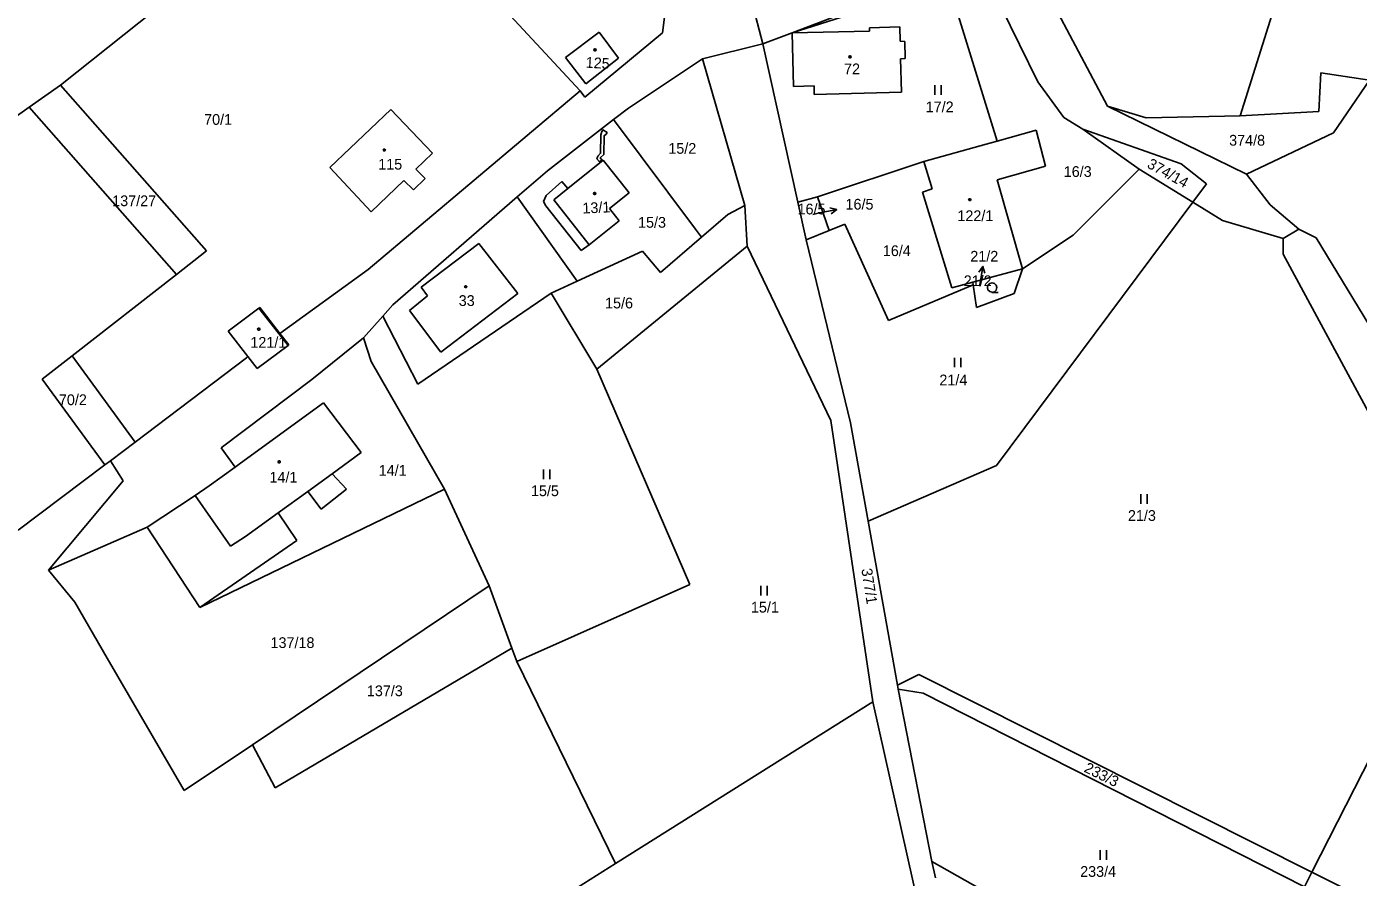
# Model space of a CAD drawing. Extents: x -811039 to -805820, y -1161436 to -1155864.
# Drawn here: x -806771.7 to -806560.9, y -1158370.8 to -1158236.2 of the extents above; entities that cross this region are included whole.
import ezdxf

# ---------------------------------------------------------------- set-up
doc = ezdxf.new("R2010")
doc.units = 0
for name, color, linetype in [('Default', 7, 'Continuous'), ('Hranice parcel', 7, 'Continuous'), ('Parcelní čísla', 7, 'Continuous'), ('Pop  PČ popisy', 7, 'Continuous'), ('Vnitřní kresba', 7, 'Continuous'), ('Věcná břemena k části', 7, 'Continuous'), ('Značky budov', 7, 'Continuous'), ('Značky kultur', 7, 'Continuous')]:
    doc.layers.add(name, color=color, linetype=linetype)

# ---------------------------------------------------------------- blocks, each defined once
blk = doc.blocks.new('304')
at = {"layer": 'Default'}
blk.add_lwpolyline([(0, 0), (-0.38, 0.1), (-0.65, 0.37), (-0.75, 0.74), (-0.65, 1.11), (-0.38, 1.38), (-0.01, 1.48), (0.36, 1.38), (0.63, 1.11), (0.73, 0.73), (0.63, 0.35), (0.36, 0.08), (-0.02, -0.02), (0.98, -0.02)], dxfattribs=at)
blk = doc.blocks.new('306')
at = {"layer": 'Default'}
for p, q in [((-0.5, 1.5), (-0.5, 0)), ((0.5, 0), (0.5, 1.5))]:
    blk.add_line(p, q, dxfattribs=at)
blk = doc.blocks.new('10292')
at = {"layer": 'Default'}
blk.add_line((0, 3), (0, 0), dxfattribs=at)
blk.add_lwpolyline([(-0.5, 2), (0, 3), (0.5, 2)], dxfattribs=at)
blk = doc.blocks.new('402')
at = {"layer": 'Default'}
blk.add_lwpolyline([(0.09, 0.15), (0.18, 0), (0.09, -0.15), (-0.09, -0.15), (-0.18, 0), (-0.09, 0.15), (0.09, 0.15)], dxfattribs=at)

msp = doc.modelspace()

# ---------------------------------------------------------------- linework, layer by layer
at = {"layer": 'Hranice parcel'}
for p, q in [((-806569.88, -1158219.21), (-806579.62, -1158250.35)), ((-806614.52, -1158222.57), (-806600.61, -1158248.81)), ((-806701.18, -1158227.97), (-806684.08, -1158246.35)), ((-806626.33, -1158227.96), (-806650.49, -1158237.2)), ((-806625.78, -1158229.31), (-806650.49, -1158237.2)), ((-806625.78, -1158229.31), (-806618.07, -1158254.33)), ((-806766.34, -1158245.5), (-806751.34, -1158233.56)), ((-806611.64, -1158244.97), (-806617.42, -1158233.13)), ((-806671.05, -1158237.22), (-806670.66, -1158234.29)), ((-806656.32, -1158234.5), (-806655.17, -1158238.94)), ((-806686.4, -1158241.1), (-806681.08, -1158237.07)), ((-806683.35, -1158247.36), (-806671.05, -1158237.22)), ((-806681.08, -1158237.07), (-806677.98, -1158241.18)), ((-806650.49, -1158237.2), (-806655.17, -1158238.94)), ((-806650.49, -1158237.2), (-806638.26, -1158236.95)), ((-806650.49, -1158237.2), (-806650.31, -1158245.68)), ((-806638.28, -1158236.39), (-806633.47, -1158236.25)), ((-806638.26, -1158236.95), (-806638.28, -1158236.39)), ((-806633.47, -1158236.25), (-806633.41, -1158238.54)), ((-806664.69, -1158241.33), (-806655.17, -1158238.94)), ((-806655.17, -1158238.94), (-806649.62, -1158263.99)), ((-806633.41, -1158238.54), (-806632.7, -1158238.55)), ((-806632.7, -1158238.55), (-806632.65, -1158241.28)), ((-806683.16, -1158245.26), (-806686.4, -1158241.1)), ((-806677.98, -1158241.18), (-806683.16, -1158245.26)), ((-806676.42, -1158249.09), (-806664.69, -1158241.33)), ((-806664.69, -1158241.33), (-806657.99, -1158264.53)), ((-806632.65, -1158241.28), (-806633.35, -1158241.33)), ((-806633.35, -1158241.33), (-806633.22, -1158246.57)), ((-806566.82, -1158243.53), (-806567.15, -1158249.63)), ((-806559.13, -1158244.68), (-806566.82, -1158243.53)), ((-806771.28, -1158248.97), (-806766.34, -1158245.5)), ((-806743.22, -1158271.7), (-806766.34, -1158245.5)), ((-806717.64, -1158274.65), (-806684.08, -1158246.35)), ((-806684.08, -1158246.35), (-806683.35, -1158247.36)), ((-806647.05, -1158245.59), (-806650.31, -1158245.68)), ((-806647.02, -1158246.96), (-806647.05, -1158245.59)), ((-806633.22, -1158246.57), (-806647.02, -1158246.96)), ((-806607.53, -1158250.61), (-806611.64, -1158244.97)), ((-806564.83, -1158253.03), (-806559.13, -1158244.68)), ((-806600.61, -1158248.81), (-806594.47, -1158250.63)), ((-806578.58, -1158259.54), (-806600.61, -1158248.81)), ((-806844.14, -1158300.03), (-806771.28, -1158248.97)), ((-806771.28, -1158248.97), (-806747.96, -1158275.4)), ((-806723.67, -1158258.49), (-806714.03, -1158249.32)), ((-806714.03, -1158249.32), (-806707.44, -1158256.22)), ((-806678.79, -1158250.93), (-806689.25, -1158259.04)), ((-806678.79, -1158250.93), (-806676.42, -1158249.09)), ((-806678.79, -1158250.93), (-806665.8, -1158268.27)), ((-806604.52, -1158252.42), (-806607.53, -1158250.61)), ((-806594.47, -1158250.63), (-806579.62, -1158250.35)), ((-806567.15, -1158249.63), (-806579.62, -1158250.35)), ((-806618.07, -1158254.33), (-806611.9, -1158252.58)), ((-806610.42, -1158258.3), (-806611.9, -1158252.58)), ((-806595.61, -1158258.78), (-806604.52, -1158252.42)), ((-806604.52, -1158252.42), (-806588.94, -1158257.91)), ((-806578.58, -1158259.54), (-806564.83, -1158253.03)), ((-806629.7, -1158257.57), (-806619.79, -1158254.82)), ((-806619.79, -1158254.82), (-806618.07, -1158254.33)), ((-806707.44, -1158256.22), (-806710.08, -1158258.75)), ((-806723.67, -1158258.49), (-806717.14, -1158265.51)), ((-806710.08, -1158258.75), (-806708.63, -1158260.25)), ((-806689.25, -1158259.04), (-806694.03, -1158263.13)), ((-806686.04, -1158261.84), (-806680.41, -1158257.34)), ((-806680.41, -1158257.34), (-806676.3, -1158262.5)), ((-806629.7, -1158257.57), (-806646.48, -1158263.13)), ((-806628.38, -1158261.89), (-806629.7, -1158257.57)), ((-806618.08, -1158260.43), (-806610.42, -1158258.3)), ((-806606.02, -1158269.18), (-806595.61, -1158258.78)), ((-806587.11, -1158264), (-806595.61, -1158258.78)), ((-806588.94, -1158257.91), (-806584.95, -1158261.1)), ((-806711.97, -1158260.56), (-806717.14, -1158265.51)), ((-806710.46, -1158262.04), (-806711.97, -1158260.56)), ((-806708.63, -1158260.25), (-806710.46, -1158262.04)), ((-806689.43, -1158262.92), (-806686.97, -1158260.72)), ((-806686.97, -1158260.72), (-806686.04, -1158261.84)), ((-806618.08, -1158260.43), (-806614.08, -1158274.51)), ((-806584.95, -1158261.1), (-806587.11, -1158264)), ((-806578.58, -1158259.54), (-806574.85, -1158264.38)), ((-806713.73, -1158280.2), (-806694.03, -1158263.13)), ((-806684.52, -1158276.47), (-806694.03, -1158263.13)), ((-806689.43, -1158262.92), (-806689.88, -1158263.88)), ((-806676.3, -1158262.5), (-806679.43, -1158265)), ((-806646.48, -1158263.13), (-806649.62, -1158263.99)), ((-806646.48, -1158263.13), (-806644.64, -1158268.47)), ((-806629.91, -1158262.41), (-806628.38, -1158261.89)), ((-806629.91, -1158262.41), (-806625.23, -1158277.52)), ((-806689.49, -1158264.59), (-806689.88, -1158263.88)), ((-806683.89, -1158271.65), (-806689.49, -1158264.59)), ((-806679.43, -1158265), (-806677.9, -1158266.93)), ((-806660.68, -1158265.92), (-806657.99, -1158264.53)), ((-806657.99, -1158264.53), (-806657.64, -1158270.92)), ((-806649.62, -1158263.99), (-806648.3, -1158269.92)), ((-806618.18, -1158305.63), (-806587.11, -1158264)), ((-806582.39, -1158266.9), (-806587.11, -1158264)), ((-806574.85, -1158264.38), (-806570.3, -1158268.26)), ((-806677.9, -1158266.93), (-806682.66, -1158270.72)), ((-806664.86, -1158269.51), (-806660.68, -1158265.92)), ((-806644.64, -1158268.47), (-806642.16, -1158267.49)), ((-806635.29, -1158282.7), (-806642.16, -1158267.49)), ((-806572.81, -1158269.71), (-806582.39, -1158266.9)), ((-806671.36, -1158275.11), (-806664.86, -1158269.51)), ((-806665.8, -1158268.27), (-806664.86, -1158269.51)), ((-806648.3, -1158269.92), (-806644.64, -1158268.47)), ((-806641.29, -1158298.89), (-806648.3, -1158269.92)), ((-806606.02, -1158269.18), (-806614.08, -1158274.51)), ((-806572.81, -1158269.71), (-806570.3, -1158268.26)), ((-806572.8, -1158272.22), (-806572.81, -1158269.71)), ((-806570.3, -1158268.26), (-806567.55, -1158269.62)), ((-806567.55, -1158269.62), (-806558.32, -1158284.79)), ((-806747.96, -1158275.4), (-806743.22, -1158271.7)), ((-806684.52, -1158276.47), (-806674.23, -1158271.75)), ((-806682.66, -1158270.72), (-806683.89, -1158271.65)), ((-806657.64, -1158270.92), (-806681.44, -1158290.41)), ((-806674.23, -1158271.75), (-806671.36, -1158275.11)), ((-806657.64, -1158270.92), (-806644.38, -1158298.52)), ((-806544.86, -1158324.01), (-806572.8, -1158272.22)), ((-806764.5, -1158288.31), (-806747.96, -1158275.4)), ((-806717.64, -1158274.65), (-806731.62, -1158284.78)), ((-806614.08, -1158274.51), (-806621.9, -1158276.62)), ((-806615.4, -1158278.42), (-806614.08, -1158274.51)), ((-806709.75, -1158292.76), (-806688.67, -1158278.37)), ((-806688.67, -1158278.37), (-806684.52, -1158276.47)), ((-806681.44, -1158290.41), (-806688.67, -1158278.37)), ((-806635.29, -1158282.7), (-806621.84, -1158277.08)), ((-806621.9, -1158276.62), (-806625.23, -1158277.52)), ((-806621.84, -1158277.08), (-806621.9, -1158276.62)), ((-806621.84, -1158277.08), (-806621.36, -1158280.63)), ((-806715.31, -1158282), (-806713.73, -1158280.2)), ((-806621.36, -1158280.63), (-806615.4, -1158278.42)), ((-806739.78, -1158284.38), (-806734.91, -1158280.74)), ((-806734.91, -1158280.74), (-806734.79, -1158280.65)), ((-806734.79, -1158280.65), (-806731.62, -1158284.78)), ((-806718.34, -1158285.46), (-806715.31, -1158282)), ((-806715.31, -1158282), (-806709.75, -1158292.76)), ((-806736.68, -1158288.42), (-806739.78, -1158284.38)), ((-806730.31, -1158286.64), (-806735.22, -1158290.32)), ((-806731.62, -1158284.78), (-806730.19, -1158286.55)), ((-806730.31, -1158286.64), (-806730.19, -1158286.55)), ((-806718.34, -1158285.46), (-806726.53, -1158292.04)), ((-806718.34, -1158285.46), (-806717.16, -1158289.2)), ((-806769.23, -1158292), (-806764.5, -1158288.31)), ((-806764.5, -1158288.31), (-806754.53, -1158301.94)), ((-806736.89, -1158288.6), (-806754.53, -1158301.94)), ((-806736.68, -1158288.42), (-806736.89, -1158288.6)), ((-806735.22, -1158290.32), (-806736.68, -1158288.42)), ((-806705.56, -1158309.37), (-806717.16, -1158289.2)), ((-806681.44, -1158290.41), (-806666.71, -1158324.45)), ((-806759.33, -1158305.54), (-806769.23, -1158292)), ((-806726.53, -1158292.04), (-806740.91, -1158302.82)), ((-806724.7, -1158295.75), (-806737.81, -1158305.26)), ((-806724.7, -1158295.75), (-806718.75, -1158303.59)), ((-806644.38, -1158298.52), (-806637.75, -1158343)), ((-806641.29, -1158298.89), (-806638.49, -1158314.46)), ((-806754.53, -1158301.94), (-806758.42, -1158304.88)), ((-806740.91, -1158302.82), (-806738.67, -1158305.89)), ((-806718.75, -1158303.59), (-806723.3, -1158306.96)), ((-806773.03, -1158315.88), (-806759.33, -1158305.54)), ((-806758.42, -1158304.88), (-806759.33, -1158305.54)), ((-806758.42, -1158304.88), (-806756.43, -1158308.08)), ((-806737.81, -1158305.26), (-806738.67, -1158305.89)), ((-806638.49, -1158314.46), (-806618.18, -1158305.63)), ((-806738.67, -1158305.89), (-806742.78, -1158308.87)), ((-806723.3, -1158306.96), (-806721.06, -1158309.4)), ((-806756.43, -1158308.08), (-806768.24, -1158322.22)), ((-806745.03, -1158310.37), (-806742.78, -1158308.87)), ((-806705.56, -1158309.37), (-806744.29, -1158328.1)), ((-806727.16, -1158309.73), (-806731.85, -1158313.12)), ((-806725.08, -1158312.56), (-806727.16, -1158309.73)), ((-806721.06, -1158309.4), (-806725.08, -1158312.56)), ((-806698.45, -1158324.65), (-806705.56, -1158309.37)), ((-806752.62, -1158315.42), (-806745.03, -1158310.37)), ((-806731.85, -1158313.12), (-806728.91, -1158317.51)), ((-806752.62, -1158315.42), (-806768.24, -1158322.22)), ((-806744.29, -1158328.1), (-806752.62, -1158315.42)), ((-806638.49, -1158314.46), (-806633.84, -1158340.37)), ((-806728.91, -1158317.51), (-806744.29, -1158328.1)), ((-806764.06, -1158327.28), (-806768.24, -1158322.22)), ((-806698.45, -1158324.65), (-806735.95, -1158349.81)), ((-806694.87, -1158334.56), (-806698.45, -1158324.65)), ((-806666.71, -1158324.45), (-806694.12, -1158336.64)), ((-806568.24, -1158369.98), (-806544.86, -1158324.01)), ((-806764.06, -1158327.28), (-806758.94, -1158336.1)), ((-806694.87, -1158334.56), (-806732.36, -1158356.65)), ((-806694.12, -1158336.64), (-806694.87, -1158334.56)), ((-806758.94, -1158336.1), (-806746.75, -1158357.06)), ((-806678.47, -1158368.59), (-806694.12, -1158336.64)), ((-806633.84, -1158340.37), (-806630.46, -1158338.72)), ((-806568.24, -1158369.98), (-806630.46, -1158338.72)), ((-806633.73, -1158341), (-806633.84, -1158340.37)), ((-806628.39, -1158368.28), (-806633.73, -1158341)), ((-806633.73, -1158341), (-806629.79, -1158341.63)), ((-806629.79, -1158341.63), (-806569.41, -1158372.27)), ((-806637.75, -1158343), (-806678.47, -1158368.59)), ((-806624.17, -1158403.51), (-806637.75, -1158343)), ((-806746.75, -1158357.06), (-806735.95, -1158349.81)), ((-806732.36, -1158356.65), (-806735.95, -1158349.81)), ((-806678.47, -1158368.59), (-806701.28, -1158382.95)), ((-806588.22, -1158390.98), (-806628.39, -1158368.28)), ((-806628.39, -1158368.28), (-806627.84, -1158370.88)), ((-806569.41, -1158372.27), (-806568.24, -1158369.98)), ((-806558.16, -1158375.01), (-806568.24, -1158369.98))]:
    msp.add_line(p, q, dxfattribs=at)
at = {"layer": 'Pop  PČ popisy'}
for p, q in [((-806647.22, -1158265.92), (-806646.4, -1158265.75)), ((-806620.82, -1158277.27), (-806620.8, -1158277.11))]:
    msp.add_line(p, q, dxfattribs=at)
at = {"layer": 'Vnitřní kresba'}
for p, q in [((-806686.04, -1158261.84), (-806688.23, -1158263.6)), ((-806688.23, -1158263.6), (-806682.66, -1158270.72)), ((-806709.22, -1158277.41), (-806700.11, -1158270.52)), ((-806700.11, -1158270.52), (-806693.93, -1158278.43)), ((-806709.22, -1158277.41), (-806708.23, -1158278.8)), ((-806708.23, -1158278.8), (-806711.11, -1158281.13)), ((-806693.93, -1158278.43), (-806706.13, -1158287.7)), ((-806730.31, -1158286.64), (-806734.91, -1158280.74)), ((-806706.13, -1158287.7), (-806711.11, -1158281.13)), ((-806723.3, -1158306.96), (-806727.16, -1158309.73)), ((-806739.44, -1158318.4), (-806745.03, -1158310.37)), ((-806731.85, -1158313.12), (-806737.02, -1158316.88)), ((-806737.02, -1158316.88), (-806739.44, -1158318.4))]:
    msp.add_line(p, q, dxfattribs=at)
at = {"layer": 'Věcná břemena k části'}
msp.add_lwpolyline([(-806681.03, -1158257.61), (-806681.42, -1158257.11), (-806681.29, -1158256.69), (-806680.85, -1158256.25), (-806680.79, -1158253.31), (-806680.64, -1158252.8), (-806680.49, -1158252.55), (-806679.82, -1158252.98), (-806679.98, -1158253.21), (-806680.29, -1158253.47), (-806680.35, -1158256.47), (-806680.88, -1158256.98), (-806680.63, -1158257.3)], close=True, dxfattribs=at)

# ---------------------------------------------------------------- block references
at = {"layer": 'Pop  PČ popisy'}
for p, rotation in [((-806646.4, -1158265.75), -78.563131), ((-806620.8, -1158277.11), -8.948759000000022)]:
    msp.add_blockref('10292', p, dxfattribs=dict(at, rotation=rotation))
at = {"layer": 'Značky budov'}
for p in [(-806681.72, -1158239.89), (-806641.36, -1158240.99), (-806715.07, -1158255.74), (-806681.78, -1158262.61), (-806622.4, -1158263.59), (-806702.18, -1158277.35), (-806734.94, -1158284.07), (-806731.71, -1158305.07)]:
    msp.add_blockref('402', p, dxfattribs=at)
at = {"layer": 'Značky kultur'}
for name, p in [('306', (-806627.41, -1158246.98)), ('304', (-806618.87, -1158278.23)), ('306', (-806624.32, -1158290.1)), ('306', (-806689.37, -1158307.79)), ('306', (-806594.81, -1158311.7)), ('306', (-806654.95, -1158326.2)), ('306', (-806601.25, -1158368.01))]:
    msp.add_blockref(name, p, dxfattribs=at)

# ---------------------------------------------------------------- texts
at = {"layer": 'Parcelní čísla'}
for s, rotation, p in [('125', 356.552, (-806683.24, -1158242.7)), ('374/14', 330.826, (-806594.47, -1158258.43)), ('13/1', 2.578, (-806683.68, -1158265.79)), ('377/1', 278.859, (-806639.57, -1158322.04)), ('233/3', 333.576, (-806604.45, -1158354.02))]:
    msp.add_text(s, height=1.7, rotation=rotation, dxfattribs=at).set_placement(p)
for s, p in [('72', (-806642.3, -1158243.75)), ('17/2', (-806629.38, -1158249.76)), ('70/1', (-806743.59, -1158251.75)), ('15/2', (-806670.12, -1158256.33)), ('374/8', (-806581.35, -1158255.04)), ('115', (-806716.03, -1158258.83)), ('16/3', (-806607.53, -1158259.99)), ('137/27', (-806758.14, -1158264.62)), ('16/5', (-806642.07, -1158265.16)), ('16/5', (-806649.66, -1158265.92)), ('122/1', (-806624.36, -1158266.98)), ('15/3', (-806674.91, -1158268.03)), ('16/4', (-806636.16, -1158272.51)), ('21/2', (-806622.32, -1158273.39)), ('21/2', (-806623.36, -1158277.27)), ('33', (-806703.29, -1158280.4)), ('15/6', (-806680.13, -1158280.79)), ('121/1', (-806736.27, -1158287.01)), ('21/4', (-806627.21, -1158292.96)), ('70/2', (-806766.58, -1158296.09)), ('14/1', (-806715.96, -1158307.26)), ('14/1', (-806733.25, -1158308.35)), ('15/5', (-806691.86, -1158310.49)), ('21/3', (-806597.37, -1158314.4)), ('15/1', (-806657.04, -1158328.9)), ('137/18', (-806733.08, -1158334.51)), ('137/3', (-806717.83, -1158342.13)), ('233/4', (-806604.93, -1158370.71))]:
    msp.add_text(s, height=1.7, dxfattribs=at).set_placement(p)

doc.saveas('drawing.dxf')
